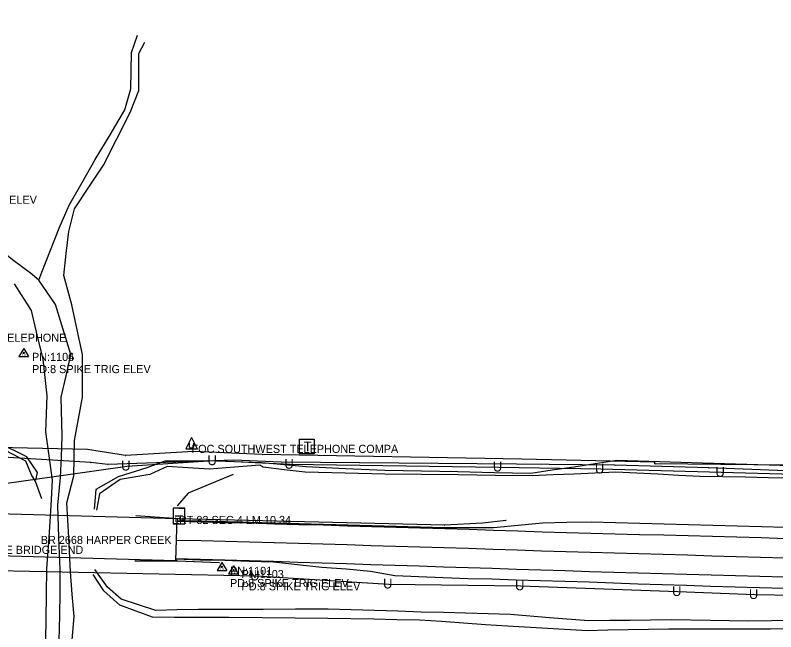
# Model space of a CAD drawing. Extents: x 976456 to 985170, y 1525951 to 1527080.
# Drawn here: x 982881.4 to 983350.2, y 1526277.2 to 1526657.2 of the extents above; entities that cross this region are included whole.
import ezdxf

# ---------------------------------------------------------------- set-up
doc = ezdxf.new("R2010")
doc.units = 0
for name, color, linetype in [('Default', 7, 'Continuous'), ('S_BRIDGE', 7, 'Continuous'), ('S_DITCHLINE', 7, 'Continuous'), ('S_EDGE_PAVEMENT', 7, 'Continuous'), ('S_FIBER_OPTIC_CABLE', 7, 'Continuous'), ('S_GUARDRAIL', 7, 'Continuous'), ('S_LOG_MILE', 7, 'Continuous'), ('S_LOG_MILE_ANNOT', 7, 'Continuous'), ('S_MSC_PT_SYM', 7, 'Continuous'), ('S_PAVEMENT_CROWN', 7, 'Continuous'), ('S_PRIMARY_CTL_ANNOT', 7, 'Continuous'), ('S_RDW_PT_SYM', 7, 'Continuous'), ('S_SECONDARY_CTL', 7, 'Continuous'), ('S_SECONDARY_CTL_ANNOT', 7, 'Continuous'), ('S_SHOULDER', 7, 'Continuous'), ('S_STR_PT_SYM', 7, 'Continuous'), ('S_STREAM', 7, 'Continuous'), ('S_SURVEY_TEXT_ANNOT', 7, 'Continuous'), ('S_TELEPHONE_UTILITIES', 7, 'Continuous'), ('S_UNDERGROUND_CABLE', 7, 'Continuous'), ('S_UTILITY_POLE_ANNOT', 7, 'Continuous'), ('S_UTL_PT_SYM', 7, 'Continuous')]:
    doc.layers.add(name, color=color, linetype=linetype)

msp = doc.modelspace()

# ---------------------------------------------------------------- linework, layer by layer
at = {"layer": 'S_BRIDGE'}
for p, q in [((982981.23, 1526346.76), (982820.35, 1526351.36)), ((982980.5, 1526321.2), (982981.23, 1526346.76)), ((982819.62, 1526325.75), (982980.5, 1526321.2))]:
    msp.add_line(p, q, dxfattribs=at)
at = {"layer": 'S_DITCHLINE'}
for points in [[(982894.18, 1526370.62), (982895.14, 1526375.36), (982888.65, 1526385.06), (982871.35, 1526393.51)], [(982897.8, 1526359.22), (982893.99, 1526369.76), (982891.4, 1526373.97), (982887.9, 1526382.42), (982871.26, 1526391.03)], [(983359.82, 1526379.42), (983346.11, 1526379.83), (983332.4, 1526380.25), (983318.69, 1526380.66), (983304.99, 1526381.07), (983291.78, 1526381.49), (983278.57, 1526381.91), (983265.37, 1526382.33), (983252.16, 1526382.75), (983238.92, 1526380.76), (983225.68, 1526378.76), (983212.45, 1526376.77), (983199.21, 1526374.78), (983176.72, 1526375.25), (983154.24, 1526375.72), (983131.75, 1526376.19), (983109.27, 1526376.66), (983084.99, 1526377.76), (983060.72, 1526378.86), (983047.12, 1526380.12), (983033.51, 1526381.38), (983032.48, 1526381.43), (983016.32, 1526382.03), (983000.17, 1526382.63), (982986.89, 1526382.48), (982973.62, 1526382.33), (982962.45, 1526378.32), (982944.81, 1526372.79), (982931.19, 1526364.95), (982930.12, 1526352.87)], [(983359.74, 1526371.92), (983345.64, 1526372.19), (983331.55, 1526372.46), (983317.45, 1526372.72), (983303.36, 1526372.99), (983290.44, 1526373.65), (983277.51, 1526374.31), (983264.59, 1526374.96), (983251.67, 1526375.62), (983238.76, 1526375.04), (983225.85, 1526374.46), (983212.94, 1526373.88), (983200.03, 1526373.29), (983177.33, 1526373.58), (983154.62, 1526373.86), (983131.91, 1526374.15), (983109.2, 1526374.44), (983084.7, 1526375.05), (983060.21, 1526375.67), (983047.19, 1526377.14), (983034.17, 1526378.61), (983032.12, 1526379.9), (983016.61, 1526378.63), (983001.11, 1526377.37), (982988.07, 1526378.2), (982975.03, 1526379.03), (982964.42, 1526374.14), (982946, 1526371.18), (982933.43, 1526362.35), (982931.52, 1526352.21)], [(983360.97, 1526278.97), (983346.96, 1526278.88), (983332.94, 1526278.79), (983308.59, 1526278.84), (983284.23, 1526278.88), (983271.73, 1526278.64), (983259.22, 1526278.39), (983246.72, 1526278.15), (983234.21, 1526277.9), (983209.56, 1526279.28), (983184.91, 1526280.65), (983171.35, 1526281.6), (983157.8, 1526282.54), (983144.24, 1526283.48), (983130.68, 1526284.42), (983116.55, 1526284.69), (983102.41, 1526284.96), (983088.28, 1526285.23), (983074.14, 1526285.5), (983053.89, 1526285.65), (983033.63, 1526285.8), (983013.38, 1526285.95), (982993.12, 1526286.11), (982979.56, 1526286.13), (982965.99, 1526286.15), (982945.87, 1526293.64), (982935.98, 1526302.52), (982929.38, 1526312.47)], [(983361.76, 1526284.16), (983347.7, 1526284), (983333.64, 1526283.84), (983309.72, 1526284.24), (983285.8, 1526284.63), (983273.11, 1526284.45), (983260.41, 1526284.27), (983247.72, 1526284.09), (983235.02, 1526283.91), (983210.84, 1526285.92), (983186.65, 1526287.93), (983172.88, 1526288.31), (983159.1, 1526288.68), (983145.33, 1526289.05), (983131.55, 1526289.42), (983117.23, 1526289.85), (983102.9, 1526290.28), (983088.58, 1526290.7), (983074.25, 1526291.13), (983054.21, 1526291.08), (983034.17, 1526291.04), (983014.12, 1526290.99), (982994.08, 1526290.95), (982981.1, 1526290.67), (982968.12, 1526290.4), (982946.71, 1526297.32), (982938.25, 1526304.69), (982930.47, 1526315.55)]]:
    msp.add_lwpolyline(points, dxfattribs=at)
at = {"layer": 'S_EDGE_PAVEMENT'}
for points in [[(982981.28, 1526345.5), (982996.27, 1526345.03), (983011.27, 1526344.67), (983026.26, 1526344.29), (983041.26, 1526343.84), (983056.33, 1526343.39), (983071.33, 1526343.12), (983086.32, 1526342.61), (983101.32, 1526342.2), (983116.31, 1526341.72), (983131.31, 1526341.33), (983146.3, 1526340.8), (983161.27, 1526340.42), (983176.26, 1526339.88), (983191.25, 1526339.39), (983206.25, 1526338.91), (983221.24, 1526338.42), (983236.23, 1526337.94), (983251.21, 1526337.66), (983266.21, 1526337.24), (983281.2, 1526336.88), (983296.2, 1526336.54), (983311.19, 1526336.08), (983311.19, 1526336.08), (983326.18, 1526335.67), (983341.18, 1526335.31), (983356.17, 1526334.78)], [(982980.66, 1526322.44), (982995.65, 1526322), (983010.64, 1526321.57), (983025.63, 1526321.09), (983040.63, 1526320.68), (983055.55, 1526320.22), (983070.54, 1526319.75), (983085.54, 1526319.31), (983100.53, 1526318.76), (983115.52, 1526318.33), (983130.51, 1526317.85), (983145.51, 1526317.36), (983160.52, 1526316.88), (983175.51, 1526316.41), (983190.5, 1526315.91), (983205.49, 1526315.43), (983205.49, 1526315.43), (983205.5, 1526315.43), (983220.49, 1526315.01), (983235.48, 1526314.43), (983250.49, 1526314.05), (983265.48, 1526313.66), (983280.48, 1526313.23), (983295.47, 1526312.78), (983295.47, 1526312.78), (983310.46, 1526312.28), (983325.46, 1526311.86), (983340.46, 1526311.52), (983355.45, 1526311.16)]]:
    msp.add_lwpolyline(points, dxfattribs=at)
at = {"layer": 'S_FIBER_OPTIC_CABLE'}
for p, q in [((982925.97, 1526389.54), (982785, 1526392.62)), ((982928.07, 1526381.47), (982789.05, 1526390.17)), ((982949.29, 1526385.91), (982925.97, 1526389.54)), ((982991.28, 1526388.32), (982949.29, 1526385.91)), ((983033.71, 1526386.54), (982991.28, 1526388.32)), ((983193.75, 1526383.68), (983033.71, 1526386.54)), ((983016.13, 1526382.97), (982938.55, 1526380.33)), ((983045.31, 1526381.77), (983016.13, 1526382.97)), ((983275.66, 1526381.75), (983193.75, 1526383.68)), ((982938.55, 1526380.33), (982928.07, 1526381.47)), ((983190.44, 1526380.58), (983045.31, 1526381.77)), ((983251.11, 1526379.96), (983190.44, 1526380.58)), ((983309.05, 1526378.18), (983251.11, 1526379.96)), ((983275.76, 1526380.75), (983275.66, 1526381.75)), ((983357.07, 1526379.84), (983275.76, 1526380.75)), ((983356.57, 1526376.42), (983309.05, 1526378.18)), ((983015.72, 1526374.18), (982988.01, 1526362.62)), ((982988.01, 1526362.62), (982981.19, 1526354.86))]:
    msp.add_line(p, q, dxfattribs=at)
at = {"layer": 'S_GUARDRAIL'}
for p, q in [((982982.09, 1526346.86), (982955.73, 1526348.73)), ((983146.14, 1526342.93), (982982.09, 1526346.86)), ((983183.99, 1526345.79), (983169.48, 1526344.12)), ((983169.48, 1526344.12), (983146.14, 1526342.93)), ((982955.24, 1526320.97), (982981.54, 1526320.87)), ((982981.54, 1526320.87), (983007.21, 1526319.95))]:
    msp.add_line(p, q, dxfattribs=at)
at = {"layer": 'S_LOG_MILE'}
for p, q in [((982982.33, 1526353.44), (982985.93, 1526353.44)), ((982979.93, 1526348.64), (982984.73, 1526348.64)), ((982982.33, 1526343.84), (982978.73, 1526343.84))]:
    msp.add_line(p, q, dxfattribs=at)
msp.add_lwpolyline([(982985.93, 1526353.44), (982978.73, 1526353.44), (982978.73, 1526343.84), (982985.93, 1526343.84)], close=True, dxfattribs=at)
at = {"layer": 'S_MSC_PT_SYM'}
msp.add_lwpolyline([(982897.15, 1526336.33), (982897.15, 1526336.38), (982897.15, 1526336.33), (982897.1, 1526336.33), (982897.15, 1526336.33), (982897.15, 1526336.28), (982897.15, 1526336.33), (982897.2, 1526336.33)], dxfattribs=at)
at = {"layer": 'S_PAVEMENT_CROWN'}
msp.add_lwpolyline([(982980.96, 1526333.61), (982995.96, 1526333.43), (983010.95, 1526333.02), (983025.95, 1526332.61), (983040.94, 1526332.17), (983055.94, 1526331.76), (983070.94, 1526331.37), (983085.93, 1526330.98), (983100.92, 1526330.49), (983115.92, 1526330.09), (983130.91, 1526329.64), (983145.91, 1526329.2), (983160.9, 1526328.7), (983175.89, 1526328.22), (983190.88, 1526327.7), (983205.87, 1526327.22), (983220.86, 1526326.74), (983235.86, 1526326.29), (983250.85, 1526325.92), (983265.84, 1526325.5), (983280.84, 1526325.04), (983295.83, 1526324.58), (983310.82, 1526324.12), (983325.82, 1526323.7), (983340.81, 1526323.18), (983355.8, 1526322.78)], dxfattribs=at)
at = {"layer": 'S_RDW_PT_SYM'}
for points in [[(982955.73, 1526348.73), (982955.73, 1526348.78), (982955.73, 1526348.73), (982955.68, 1526348.73), (982955.73, 1526348.73), (982955.73, 1526348.68), (982955.73, 1526348.73), (982955.78, 1526348.73)], [(982982.09, 1526346.86), (982982.09, 1526346.91), (982982.09, 1526346.86), (982982.04, 1526346.86), (982982.09, 1526346.86), (982982.09, 1526346.81), (982982.09, 1526346.86), (982982.14, 1526346.86)], [(983183.99, 1526345.79), (983183.99, 1526345.84), (983183.99, 1526345.79), (983183.94, 1526345.79), (983183.99, 1526345.79), (983183.99, 1526345.74), (983183.99, 1526345.79), (983184.04, 1526345.79)], [(983146.14, 1526342.93), (983146.14, 1526342.98), (983146.14, 1526342.93), (983146.09, 1526342.93), (983146.14, 1526342.93), (983146.14, 1526342.88), (983146.14, 1526342.93), (983146.19, 1526342.93)], [(983169.48, 1526344.12), (983169.48, 1526344.17), (983169.48, 1526344.12), (983169.43, 1526344.12), (983169.48, 1526344.12), (983169.48, 1526344.07), (983169.48, 1526344.12), (983169.53, 1526344.12)], [(982955.24, 1526320.97), (982955.24, 1526321.02), (982955.24, 1526320.97), (982955.19, 1526320.97), (982955.24, 1526320.97), (982955.24, 1526320.92), (982955.24, 1526320.97), (982955.29, 1526320.97)], [(982981.54, 1526320.87), (982981.54, 1526320.92), (982981.54, 1526320.87), (982981.49, 1526320.87), (982981.54, 1526320.87), (982981.54, 1526320.82), (982981.54, 1526320.87), (982981.59, 1526320.87)], [(983007.21, 1526319.95), (983007.21, 1526320), (983007.21, 1526319.95), (983007.16, 1526319.95), (983007.21, 1526319.95), (983007.21, 1526319.9), (983007.21, 1526319.95), (983007.26, 1526319.95)]]:
    msp.add_lwpolyline(points, dxfattribs=at)
at = {"layer": 'S_SECONDARY_CTL'}
for p, q in [((982886.73, 1526451.77), (982883.72, 1526446.82)), ((982886.73, 1526451.75), (982883.72, 1526446.8)), ((982886.73, 1526451.77), (982889.68, 1526446.82)), ((982886.73, 1526451.75), (982889.68, 1526446.8)), ((982883.72, 1526446.82), (982889.68, 1526446.82)), ((982883.72, 1526446.8), (982889.68, 1526446.8)), ((983008.8, 1526319.87), (983005.79, 1526314.92)), ((983008.8, 1526319.87), (983011.75, 1526314.92)), ((983015.95, 1526317.9), (983012.94, 1526312.95)), ((983015.95, 1526317.9), (983018.9, 1526312.95)), ((983005.79, 1526314.92), (983011.75, 1526314.92)), ((983012.94, 1526312.95), (983018.9, 1526312.95))]:
    msp.add_line(p, q, dxfattribs=at)
for centre, radius in [((982886.73, 1526449.16), 0.311), ((982886.73, 1526449.14), 0.311), ((982886.73, 1526449.16), 0.183), ((982886.73, 1526449.14), 0.183), ((982886.73, 1526449.14), 0.103), ((982886.73, 1526449.16), 0.103), ((983008.8, 1526317.26), 0.311), ((983008.8, 1526317.26), 0.183), ((983008.8, 1526317.26), 0.103), ((983015.95, 1526315.29), 0.311), ((983015.95, 1526315.29), 0.183), ((983015.95, 1526315.29), 0.103)]:
    msp.add_circle(centre, radius, dxfattribs=at)
at = {"layer": 'S_SHOULDER'}
for points in [[(982981.29, 1526345.9), (982996.29, 1526345.55), (983011.29, 1526345.2), (983026.28, 1526344.81), (983041.27, 1526344.34), (983056.35, 1526343.9), (983071.35, 1526343.63), (983086.34, 1526343.12), (983101.34, 1526342.71), (983116.33, 1526342.23), (983131.32, 1526341.83), (983146.32, 1526341.46), (983161.31, 1526341.44), (983176.32, 1526341.49), (983191.37, 1526342.91), (983206.42, 1526344.3), (983221.44, 1526344.75), (983236.46, 1526344.9), (983251.42, 1526344.61), (983266.42, 1526344.12), (983281.41, 1526343.69), (983296.41, 1526343.36), (983311.4, 1526342.95), (983326.39, 1526342.53), (983341.38, 1526342.17), (983356.37, 1526341.65)], [(982980.65, 1526322.1), (982995.65, 1526321.66), (983010.64, 1526321.33), (983025.63, 1526320.74), (983040.62, 1526320.26), (983055.51, 1526318.78), (983070.46, 1526317.09), (983085.44, 1526316.05), (983100.39, 1526314.5), (983115.32, 1526311.98), (983130.3, 1526311.38), (983145.29, 1526310.77), (983160.31, 1526310.15), (983175.3, 1526309.77), (983190.29, 1526309.22), (983205.29, 1526308.9), (983220.28, 1526308.51), (983235.27, 1526307.94), (983250.29, 1526307.32), (983265.28, 1526306.78), (983280.27, 1526306.35), (983295.26, 1526305.86), (983310.25, 1526305.32), (983325.25, 1526304.9), (983340.25, 1526304.51), (983355.24, 1526304.2)]]:
    msp.add_lwpolyline(points, dxfattribs=at)
at = {"layer": 'S_STR_PT_SYM'}
for points in [[(982981.23, 1526346.76), (982981.23, 1526347.26), (982981.23, 1526346.76), (982980.73, 1526346.76), (982981.23, 1526346.76), (982981.23, 1526346.26), (982981.23, 1526346.76), (982981.73, 1526346.76)], [(982980.5, 1526321.2), (982980.5, 1526321.7), (982980.5, 1526321.2), (982980, 1526321.2), (982980.5, 1526321.2), (982980.5, 1526320.7), (982980.5, 1526321.2), (982981, 1526321.2)]]:
    msp.add_lwpolyline(points, dxfattribs=at)
at = {"layer": 'S_STREAM'}
for points in [[(982895.93, 1526493.93), (982890.81, 1526498.19), (982879.82, 1526506.47), (982865.52, 1526517.79), (982853.63, 1526524.12), (982841.74, 1526530.45), (982825.71, 1526538.15), (982809.69, 1526545.84), (982793.64, 1526562.16), (982787.89, 1526573.62), (982782.15, 1526585.07), (982770.67, 1526605.65), (982759.87, 1526625.52), (982754.88, 1526639.53), (982743.5, 1526657.24)], [(982908.43, 1526271.62), (982908.96, 1526287.18), (982909.03, 1526301.4), (982909.1, 1526315.63), (982908.37, 1526335.43), (982907.64, 1526355.23), (982909.41, 1526372.23), (982909.88, 1526385.04), (982910.35, 1526397.84), (982909.82, 1526421.91), (982912.77, 1526435.03), (982915.73, 1526448.15), (982910.94, 1526463.5), (982906.15, 1526478.85), (982895.93, 1526493.93), (982897.9, 1526498.78), (982903.21, 1526512.43), (982908.53, 1526526.08), (982914.59, 1526540.1), (982922.69, 1526554.22), (982930.78, 1526568.33), (982939.92, 1526583.6), (982949.06, 1526598.87), (982952.71, 1526611.93), (982953.18, 1526634.26), (982956.79, 1526644.98)], [(982916.38, 1526269.85), (982917.7, 1526286.69), (982916.59, 1526300.39), (982915.49, 1526314.1), (982914.35, 1526335.41), (982913.22, 1526356.73), (982917.62, 1526373.4), (982917.89, 1526395.02), (982920.36, 1526408.38), (982922.82, 1526421.75), (982922.83, 1526434.9), (982922.85, 1526448.06), (982919.54, 1526463.38), (982916.23, 1526478.69), (982911.37, 1526496.77), (982912.87, 1526510.34), (982914.36, 1526523.91), (982917.9, 1526537.81), (982926.82, 1526551.31), (982935.75, 1526564.81), (982944, 1526581.08), (982952.25, 1526597.34), (982957.68, 1526610.8), (982957.64, 1526633.74), (982961.3, 1526640.7)], [(982900.18, 1526272.17), (982900.46, 1526284.84), (982900.72, 1526300.39), (982900.97, 1526315.94), (982902.27, 1526335.36), (982903.57, 1526354.79), (982904.47, 1526370.66), (982902.34, 1526385.59), (982900.2, 1526400.53), (982901.16, 1526422.7), (982898.62, 1526445.17), (982894.99, 1526460.16), (982891.35, 1526475.16), (982880.94, 1526491.73)]]:
    msp.add_lwpolyline(points, dxfattribs=at)
at = {"layer": 'S_TELEPHONE_UTILITIES'}
msp.add_lwpolyline([(983056.63, 1526386.88), (983056.63, 1526395.88), (983065.63, 1526395.88), (983065.63, 1526386.88)], close=True, dxfattribs=at)
at = {"layer": 'S_UNDERGROUND_CABLE'}
for p, q in [((982990.08, 1526396.99), (982986.56, 1526389.9)), ((982990.08, 1526396.99), (982993.57, 1526389.9)), ((982988.88, 1526391.14), (982988.88, 1526393.58)), ((982991.24, 1526393.58), (982991.24, 1526391.14)), ((982986.56, 1526389.9), (982993.57, 1526389.9)), ((982989.5, 1526390.48), (982988.88, 1526391.14)), ((982990.7, 1526390.48), (982989.5, 1526390.48)), ((982991.24, 1526391.14), (982990.7, 1526390.48)), ((983003.54, 1526382.49), (982950.31, 1526379.17)), ((983050.97, 1526380.27), (983003.54, 1526382.49)), ((982950.31, 1526379.17), (982818.47, 1526360.31)), ((983179.45, 1526378.55), (983050.97, 1526380.27)), ((983242.4, 1526377.37), (983179.45, 1526378.55)), ((983316.69, 1526375.31), (983242.4, 1526377.37)), ((983367.37, 1526373.97), (983316.69, 1526375.31)), ((983029.83, 1526311.42), (982804.96, 1526316.13)), ((983111.79, 1526306.46), (983029.83, 1526311.42)), ((983193.16, 1526305.37), (983111.79, 1526306.46)), ((983289.95, 1526301.8), (983193.16, 1526305.37)), ((983337.28, 1526299.97), (983289.95, 1526301.8)), ((983439.12, 1526298.37), (983337.28, 1526299.97))]:
    msp.add_line(p, q, dxfattribs=at)
at = {"layer": 'S_UTL_PT_SYM'}
for points in [[(982925.97, 1526389.54), (982925.97, 1526389.59), (982925.97, 1526389.54), (982925.92, 1526389.54), (982925.97, 1526389.54), (982925.97, 1526389.49), (982925.97, 1526389.54), (982926.02, 1526389.54)], [(982991.28, 1526388.32), (982991.28, 1526388.37), (982991.28, 1526388.32), (982991.23, 1526388.32), (982991.28, 1526388.32), (982991.28, 1526388.27), (982991.28, 1526388.32), (982991.33, 1526388.32)], [(983033.71, 1526386.54), (983033.71, 1526386.59), (983033.71, 1526386.54), (983033.65, 1526386.54), (983033.71, 1526386.54), (983033.71, 1526386.49), (983033.71, 1526386.54), (983033.76, 1526386.54)], [(982949.29, 1526385.91), (982949.29, 1526385.96), (982949.29, 1526385.91), (982949.24, 1526385.91), (982949.29, 1526385.91), (982949.29, 1526385.86), (982949.29, 1526385.91), (982949.34, 1526385.91)], [(983016.13, 1526382.97), (983016.13, 1526383.02), (983016.13, 1526382.97), (983016.08, 1526382.97), (983016.13, 1526382.97), (983016.13, 1526382.92), (983016.13, 1526382.97), (983016.18, 1526382.97)], [(983193.75, 1526383.68), (983193.75, 1526383.73), (983193.75, 1526383.68), (983193.7, 1526383.68), (983193.75, 1526383.68), (983193.75, 1526383.63), (983193.75, 1526383.68), (983193.8, 1526383.68)], [(982928.07, 1526381.47), (982928.07, 1526381.52), (982928.07, 1526381.47), (982928.02, 1526381.47), (982928.07, 1526381.47), (982928.07, 1526381.42), (982928.07, 1526381.47), (982928.12, 1526381.47)], [(982938.55, 1526380.33), (982938.55, 1526380.38), (982938.55, 1526380.33), (982938.5, 1526380.33), (982938.55, 1526380.33), (982938.55, 1526380.28), (982938.55, 1526380.33), (982938.6, 1526380.33)], [(983045.31, 1526381.77), (983045.31, 1526381.82), (983045.31, 1526381.77), (983045.26, 1526381.77), (983045.31, 1526381.77), (983045.31, 1526381.72), (983045.31, 1526381.77), (983045.36, 1526381.77)], [(983190.44, 1526380.58), (983190.44, 1526380.63), (983190.44, 1526380.58), (983190.39, 1526380.58), (983190.44, 1526380.58), (983190.44, 1526380.53), (983190.44, 1526380.58), (983190.49, 1526380.58)], [(983251.11, 1526379.96), (983251.11, 1526380.01), (983251.11, 1526379.96), (983251.06, 1526379.96), (983251.11, 1526379.96), (983251.11, 1526379.91), (983251.11, 1526379.96), (983251.16, 1526379.96)], [(983275.66, 1526381.75), (983275.66, 1526381.8), (983275.66, 1526381.75), (983275.61, 1526381.75), (983275.66, 1526381.75), (983275.66, 1526381.7), (983275.66, 1526381.75), (983275.71, 1526381.75)], [(983275.76, 1526380.75), (983275.76, 1526380.8), (983275.76, 1526380.75), (983275.71, 1526380.75), (983275.76, 1526380.75), (983275.76, 1526380.7), (983275.76, 1526380.75), (983275.81, 1526380.75)], [(983309.05, 1526378.18), (983309.05, 1526378.23), (983309.05, 1526378.18), (983309, 1526378.18), (983309.05, 1526378.18), (983309.05, 1526378.13), (983309.05, 1526378.18), (983309.1, 1526378.18)], [(983015.72, 1526374.18), (983015.72, 1526374.23), (983015.72, 1526374.18), (983015.67, 1526374.18), (983015.72, 1526374.18), (983015.72, 1526374.13), (983015.72, 1526374.18), (983015.77, 1526374.18)], [(982988.01, 1526362.62), (982988.01, 1526362.67), (982988.01, 1526362.62), (982987.96, 1526362.62), (982988.01, 1526362.62), (982988.01, 1526362.57), (982988.01, 1526362.62), (982988.06, 1526362.62)], [(982981.19, 1526354.86), (982981.19, 1526354.91), (982981.19, 1526354.86), (982981.14, 1526354.86), (982981.19, 1526354.86), (982981.19, 1526354.81), (982981.19, 1526354.86), (982981.24, 1526354.86)]]:
    msp.add_lwpolyline(points, dxfattribs=at)

# ---------------------------------------------------------------- texts
at = {"layer": 'Default'}
for p in [(982946.68, 1526376.63), (982999.91, 1526379.95), (983047.34, 1526377.73), (983175.82, 1526376), (983238.77, 1526374.83), (983313.06, 1526372.76), (983026.2, 1526308.88), (983108.16, 1526303.92), (983189.53, 1526302.83), (983286.32, 1526299.26), (983333.65, 1526297.42)]:
    msp.add_text('U', height=6, rotation=360, dxfattribs=at).set_placement(p)
at = {"layer": 'S_LOG_MILE'}
msp.add_text('LM', height=3, rotation=360, dxfattribs=at).set_placement((982979.79, 1526344.8))
at = {"layer": 'S_LOG_MILE_ANNOT'}
msp.add_text('RT 82 SEC 4 LM 10.34', height=5, dxfattribs=at).set_placement((982982.33, 1526343.64))
at = {"layer": 'S_PRIMARY_CTL_ANNOT'}
msp.add_text('PD:CONCRETE BRIDGE END', height=5, dxfattribs=at).set_placement((982831.23, 1526325.22))
at = {"layer": 'S_SECONDARY_CTL'}
for p in [(982885.52, 1526447.15), (982885.52, 1526447.13), (983007.6, 1526315.25), (983014.74, 1526313.28)]:
    msp.add_text('TV', height=1.5, rotation=360, dxfattribs=at).set_placement(p)
at = {"layer": 'S_SECONDARY_CTL_ANNOT'}
for s, p in [('PD:RBR ALUM CAP 8 SPIKE TRIG ELEV', (982769.56, 1526541.01)), ('PN:1106', (982891.73, 1526444.16)), ('PN:1104', (982891.73, 1526444.14)), ('PD:8 SPIKE TRIG ELEV', (982891.73, 1526436.66)), ('PD:8 SPIKE TRIG ELEV', (982891.73, 1526436.64)), ('PN:1101', (983013.8, 1526312.26)), ('PN:1103', (983020.95, 1526310.29)), ('PD:8 SPIKE TRIG ELEV', (983013.8, 1526304.76)), ('PD:8 SPIKE TRIG ELEV', (983020.95, 1526302.79))]:
    msp.add_text(s, height=5, dxfattribs=at).set_placement(p)
at = {"layer": 'S_SURVEY_TEXT_ANNOT'}
msp.add_text('BR 2668 HARPER CREEK', height=5, dxfattribs=at).set_placement((982897.15, 1526331.33))
at = {"layer": 'S_TELEPHONE_UTILITIES'}
msp.add_text('T', height=6, rotation=360, dxfattribs=at).set_placement((983059.19, 1526388.38))
at = {"layer": 'S_UTILITY_POLE_ANNOT'}
for s, p in [('TY:FOC SOUTH ARKANSAS TELEPHONE', (982782.49, 1526455.99)), ('FOC SOUTHWEST TELEPHONE COMPA', (982990.08, 1526387.46))]:
    msp.add_text(s, height=5, dxfattribs=at).set_placement(p)

doc.saveas('drawing.dxf')
